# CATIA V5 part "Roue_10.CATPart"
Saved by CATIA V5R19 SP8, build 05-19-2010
Part number: Roue_10
Nomenclature: 70_R10
Bounding box of the stored display mesh (mm): x -3.239 to 3.23, y -3.248 to 3.169, z 0 to 2
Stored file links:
  C:\Users\rphgr\Desktop\0_Tapis_TC520B_vitesse\Roue_10.CATPart
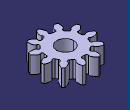
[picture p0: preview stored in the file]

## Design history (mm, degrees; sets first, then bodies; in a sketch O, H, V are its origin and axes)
External parameters (linked from other documents)
  External.Module = 0.5 mm
  External.Z = 11
  External.DiamPrimitif = 5.5 mm {= External.Module *External.Z}
  External.AnglePression = 20 deg
  External.x = 0
  External.DeportDenture = 0 mm {= External.x *External.Module}
  External.DiamBase = 5.1683 mm {= External.DiamPrimitif *cos(External.AnglePression )}
  External.DiamPied = 4.25 mm {= External.DiamPrimitif -2.5*External.Module +2*External.DeportDenture}
  External.DiamTete = 6.5 mm {= External.DiamPrimitif +2*External.Module +2*External.DeportDenture}
  External.PhiPrimitif = 0.854 deg {= atan((sin(External.ThetaPrimitif*1rad)-External.ThetaPrimitif*cos(External.ThetaPrimitif*1rad))/(cos(External.ThetaPrimitif*1rad)+External.ThetaPrimitif*sin(External.ThetaPrimitif*1rad)))}
  External.PhiTete = 6.3669 deg {= atan((sin(External.ThetaTete*1rad)-External.ThetaTete*cos(External.ThetaTete*1rad))/(cos(External.ThetaTete*1rad)+External.ThetaTete*sin(External.ThetaTete*1rad)))}
  External.PhiSymetrie = 8.1818 deg {= 180*1 deg/(2*External.Z )}
  External.CongePied = 0.19 mm {= 0.38*External.Module}
  External.AlphaCopie = 32.7273 deg {= 360*1 deg/External.Z}
  External.AlphaSymetrieCopie = 16.3636 deg {= External.AlphaCopie /2}
  External.CoeffQualiteEngrenage = 7
  External.LargeurDenture = 2 mm
  External.ThetaPrimitif = 0.36397 {= sqrt(abs((External.DiamPrimitif*External.DiamPrimitif)/(External.DiamBase *External.DiamBase )-1))}
  External.ThetaTete = 0.762706 {= sqrt(abs((External.DiamTete*External.DiamTete)/(External.DiamBase *External.DiamBase )-1) )}
  External.Di = 5.3342 mm {= (External.DiamBase +External.DiamPrimitif )/2}
  External.Thetai = 0.255358 {= sqrt(abs((External.Di*External.Di)/(External.DiamBase*External.DiamBase)-1))}
  External.Phii = 0.3061 deg {= atan((sin(External.Thetai*1rad)-External.Thetai*cos(External.Thetai*1rad))/(cos(External.Thetai*1rad)+External.Thetai*sin(External.Thetai*1rad)))}
  External.Dj = 6 mm {= (External.DiamTete+External.DiamPrimitif)/2}
  External.Thetaj = 0.589693 {= sqrt(abs((External.Dj*External.Dj)/(External.DiamBase*External.DiamBase)-1))}
  External.Phij = 3.2594 deg {= atan((sin(External.Thetaj*1rad)-External.Thetaj*cos(External.Thetaj*1rad))/(cos(External.Thetaj*1rad)+External.Thetaj*sin(External.Thetaj*1rad)))}
  External.Dk = 5.2512 mm {= (External.Di+External.DiamBase)/2}
  External.Thetak = 0.179851 {= sqrt(abs((External.Dk*External.Dk)/(External.DiamBase*External.DiamBase)-1))}
  External.Phik = 0.109 deg {= atan((sin(External.Thetak*1rad)-External.Thetak*cos(External.Thetak*1rad))/(cos(External.Thetak*1rad)+External.Thetak*sin(External.Thetak*1rad)))}
  External.Dl = 5.4171 mm {= (External.DiamPrimitif+External.Di)/2}
  External.Thetal = 0.31398 {= sqrt(abs((External.Dl*External.Dl)/(External.DiamBase*External.DiamBase)-1))}
  External.Phil = 0.5585 deg {= atan((sin(External.Thetal*1rad)-External.Thetal*cos(External.Thetal*1rad))/(cos(External.Thetal*1rad)+External.Thetal*sin(External.Thetal*1rad)))}
  External.Dm = 5.75 mm {= (External.Dj+External.DiamPrimitif)/2}
  External.Thetam = 0.487613 {= sqrt(abs((External.Dm*External.Dm)/(External.DiamBase*External.DiamBase)-1))}
  External.Phim = 1.9437 deg {= atan((sin(External.Thetam*1rad)-External.Thetam*cos(External.Thetam*1rad))/(cos(External.Thetam*1rad)+External.Thetam*sin(External.Thetam*1rad)))}
  External.Dn = 6.25 mm {= (External.DiamTete+External.Dj)/2}
  External.Thetan = 0.679992 {= sqrt(abs((External.Dn*External.Dn)/(External.DiamBase*External.DiamBase)-1))}
  External.Phin = 4.7453 deg {= atan((sin(External.Thetan*1rad)-External.Thetan*cos(External.Thetan*1rad))/(cos(External.Thetan*1rad)+External.Thetan*sin(External.Thetan*1rad)))}
  External.DiametreAlesage = 2 mm
Body1 (main body)
  Sketch1 on xy-plane, origin (0, 0, 0), H (1, 0, 0), V (0, 1, 0)
    construction circle A1 centre (0, 0) radius 2.75
    construction circle A2 centre (0, 0) radius 2.5842
    construction circle A3 centre (0, 0) radius 2.125
    construction circle A4 centre (0, 0) radius 3.25
    point P1 (2.5842, 0)
    construction line L1 (2.5842, 0) -> (0, 0)
    point P2 (2.7497, 0.041)
    construction line L2 (2.7497, 0.041) -> (0, 0)
    point P3 (3.23, 0.3604)
    construction line L3 (3.23, 0.3604) -> (0, 0)
    construction line L4 (2.5842, 0) -> (2.5842, 3.9367)
    point P4 (2.5842, 0)
    point P6 (2.4186, 0.041)
    construction line L5 (3.23, 0.3604) -> (2.7497, 0.041)
    point P7 (2.9898, 0.2007)
    point P8 (2.1785, 0.2007)
    spline S1 through (2.1785, 0.2007) (2.4186, 0.041) (2.5842, 0) (2.6256, 0.005) (2.667, 0.0142) (2.7084, 0.0264) (2.7497, 0.041) (2.8733, 0.0975) (2.9951, 0.1706) (3.1143, 0.2585) (3.23, 0.3604)
    construction line L6 (0, 0) -> (5.2089, 0.8284)
    spline S2 through (2.1333, 0.485) (2.312, 0.7113) (2.4567, 0.8016) (2.4976, 0.8097) (2.5399, 0.8138) (2.583, 0.8151) (2.6268, 0.814) (2.7619, 0.7986) (2.9003, 0.767) (3.0409, 0.7203) (3.1824, 0.6593)
    arc A5 centre (2.312, -0.1175) radius 0.19 from (2.4032, 0.0492) to (2.1223, -0.1079) ccw
    point P11 (2.1223, -0.1079)
    arc A6 centre (0, 0) radius 3.25 from (3.23, 0.3604) to (3.1824, 0.6593) ccw
    point P13 (3.1824, 0.6593)
    arc A7 centre (2.1615, 0.8289) radius 0.19 from (1.9841, 0.7609) to (2.2999, 0.6988) ccw
    point P15 (1.9841, 0.7609)
    construction line L7 (0, 0) -> (3.8692, 1.8372)
    construction line L8 (0, 0) -> (5.084, -0.6538)
    point P19 (1.9196, 0.9115)
    arc A8 centre (0, 0) radius 2.125 from (1.9841, 0.7609) to (1.9196, 0.9115) ccw
    point P20 (2.1076, -0.271)
    arc A9 centre (0, 0) radius 2.125 from (2.1076, -0.271) to (2.1223, -0.1079) ccw
    line L9 (1.9196, 0.9115) -> (0, 0)
    line L10 (2.1076, -0.271) -> (0, 0)
    construction circle A10 centre (0, 0) radius 2.6671
    construction line L11 (0, 0) -> (2.5698, 0.0137)
    point P22 (2.667, 0.0142)
    construction circle A11 centre (0, 0) radius 3
    construction line L12 (0, 0) -> (4.0126, 0.2285)
    point P24 (2.9951, 0.1706)
    point P25 (2.9951, 0.1706)
    point P26 (2.9003, 0.767)
    point P27 (2.5399, 0.8138)
    construction circle A12 centre (0, 0) radius 2.6256
    construction line L13 (0, 0) -> (48.2618, 0.0918)
    point P29 (2.4976, 0.8097)
    construction line L14 (0, 0) -> (63.1845, 10.0479)
    point P31 (2.6256, 0.005)
    construction circle A13 centre (0, 0) radius 2.7085
    construction line L15 (0, 0) -> (57.3607, 0.5591)
    point P33 (2.7084, 0.0264)
    point P34 (2.583, 0.8151)
    construction circle A14 centre (0, 0) radius 2.875
    construction line L16 (0, 0) -> (65.6729, 2.2287)
    point P36 (2.8733, 0.0975)
    point P37 (2.7619, 0.7986)
    construction circle A15 centre (0, 0) radius 3.125
    axis line L17 (0, 0) -> (59.1475, 4.9099)
    point P39 (3.0409, 0.7203)
    point P40 (3.1143, 0.2585)
    point P42 (2.1785, 0.2007)
    point P43 (2.4186, 0.041)
    point P44 (2.5842, 0)
    point P45 (2.7497, 0.041)
    point P46 (3.23, 0.3604)
    point P47 (3.1824, 0.6593)
    point P48 (2.1333, 0.485)
    point P49 (2.6268, 0.814)
    point P50 (2.4567, 0.8016)
    point P51 (2.312, 0.7113)
    point P52 (2.667, 0.0142)
    point P53 (2.9951, 0.1706)
    point P54 (2.5399, 0.8138)
    point P55 (2.9003, 0.767)
    point P56 (2.6256, 0.005)
    point P57 (2.4976, 0.8097)
    point P58 (2.7084, 0.0264)
    point P59 (2.583, 0.8151)
    point P60 (2.8733, 0.0975)
    point P61 (2.7619, 0.7986)
    point P62 (3.1143, 0.2585)
    point P63 (3.0409, 0.7203)
    radius A1 = 2.75 {= External.DiamPrimitif /2}
    radius A2 = 2.5842 {= External.DiamBase /2}
    radius A3 = 2.125 {= External.DiamPied /2}
    radius A4 = 3.25 {= External.DiamTete /2}
    angle L2 L1 = 0.854 {= External.PhiPrimitif}
    angle L3 L1 = 6.3669 {= External.PhiTete}
    angle L4 L1 = 90
    radius A5 = 0.19 {= External.CongePied}
    radius A7 = 0.19 {= External.CongePied}
    angle L7 L6 = 16.3636 {= External.AlphaSymetrieCopie}
    angle L2 L6 = 8.1818 {= External.PhiSymetrie}
    radius A10 = 2.6671 {= External.Di /2}
    angle L11 L1 = 0.3061 {= External.Phii}
    radius A11 = 3 {= External.Dj /2}
    angle L12 L1 = 3.2594 {= External.Phij}
    radius A12 = 2.6256 {= External.Dk/2}
    angle L13 L1 = 0.109 {= External.Phik}
    angle L14 L2 = 8.1818 {= External.PhiSymetrie}
    radius A13 = 2.7085 {= External.Dl /2}
    angle L15 L1 = 0.5585 {= External.Phil}
    radius A14 = 2.875 {= External.Dm /2}
    angle L16 L1 = 1.9437 {= External.Phim}
    radius A15 = 3.125 {= External.Dn/2}
    angle L17 L1 = 4.7453 {= External.Phin}
    coincidence: P1 A2, P1 H, P2 A1, P3 A4, P4 A2, P7 L5, P42 P8, P43 P6, P44 P1, P45 L5, P45 L2, P46 L5, P46 L3, P11 A3, P47 P13, P15 A3, P19 L7, P19 A3, P20 L8, P20 A3, P3 P46, P22 L11, P22 A10, P52 P22, P24 L12, P24 A11, P53 P24, P25 P53, P54 P27, P55 P26, P31 L13, P31 A12, P56 P31, P57 P29, P33 L15, P33 A13, P58 P33, P59 P34, P36 L16, P36 A14, P60 P36, P61 P37, P40 L17, P40 A15, P62 P40, P63 P39, O L9, O L10
    horizontal: L1 H
    tangency: L4 A2, A5 A3, A5 S1, A7 A3, A7 S2, A8 A5, A9 A5
    symmetry: P6 P2 L4, P8 P7 L4, P46 P47 L6, P42 P48 L6, P45 P49 L6, P44 P50 L6, P43 P51 L6, L8 L7 L6, P26 P25 L6, P27 P22 L6, P29 P31 L14, P34 P33 L14, P37 P36 L14, P39 P40 L14
    midpoint: P7 L5
    parallelism: L9 L7, L10 L8
    concentricity: A10 A2, A11 A1
  Pad1: profile Sketch1, direction (0, 0, 1), length 2 {= External.LargeurDenture}
  CircPattern1 "Roue Dentée": of Pad1, instances 11 {= External.Z}, angular step 32.7273 {= External.AlphaCopie}, axis from Z axis
  Body2
    Sketch2 on xy-plane, origin (0, 0, 0), H (1, 0, 0), V (0, 1, 0)
      circle A1 centre (0, 0) radius 1
      radius A1 = 1 {= External.DiametreAlesage /2}
    Pad2: profile Sketch2, direction (0, 0, 1), length 4 {= 2*External.LargeurDenture}
  Remove1: tool Body2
